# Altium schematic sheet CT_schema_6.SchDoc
size 251 x 159 mm
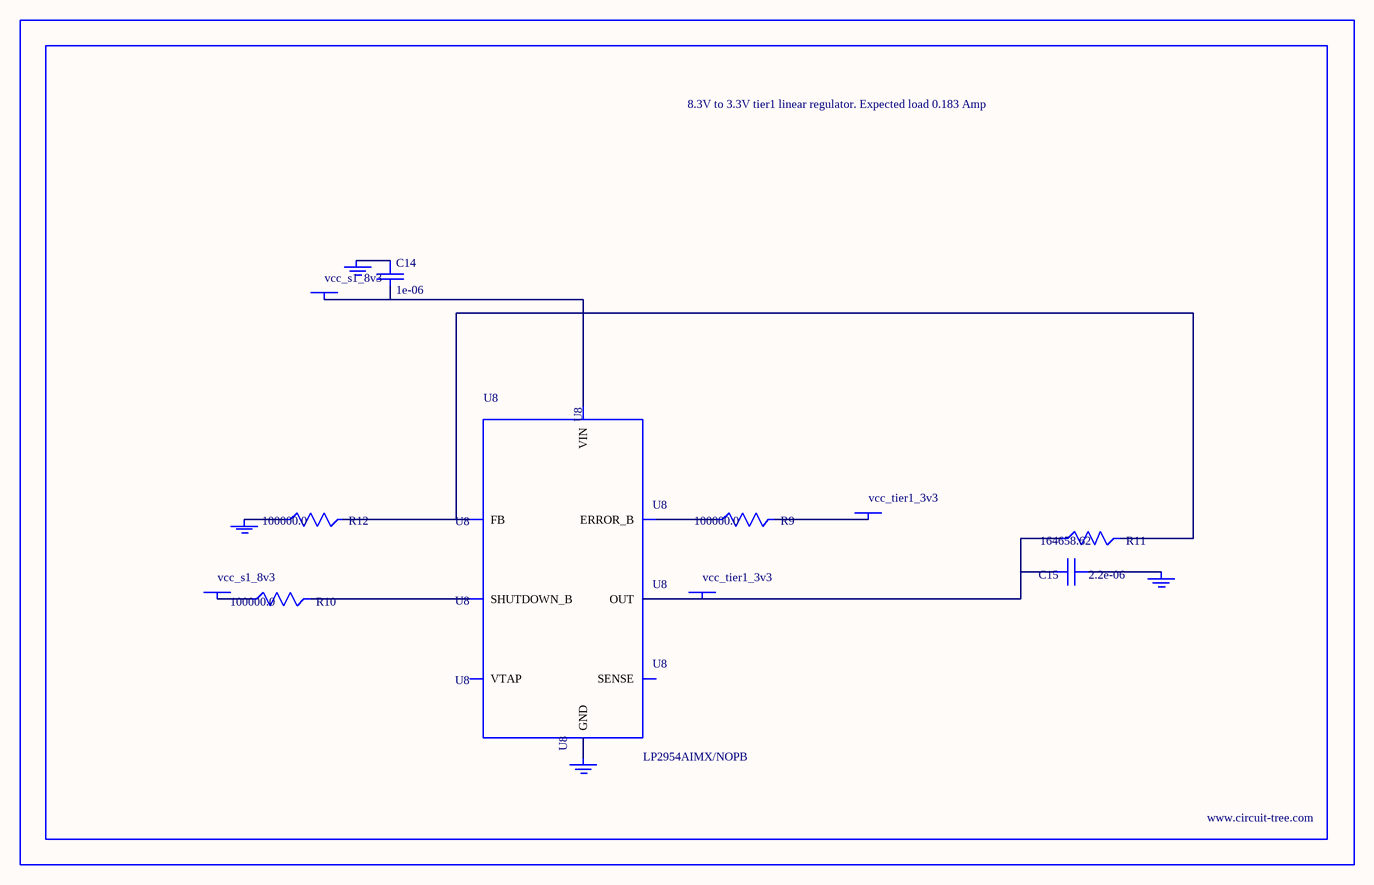
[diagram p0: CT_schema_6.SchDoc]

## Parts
BORDER5  (no value)
C14  1e-06  [EXV-9B]
C15  2.2e-06  [EXV-9B]
GND_INSTANCE_5_0  (no value)
GND_INSTANCE_5_1  (no value)
GND_INSTANCE_5_2  (no value)
GND_INSTANCE_5_3  (no value)
POWER_INSTANCE_5_0  vcc_s1_8v3
POWER_INSTANCE_5_1  vcc_tier1_3v3
POWER_INSTANCE_5_2  vcc_s1_8v3
POWER_INSTANCE_5_3  vcc_tier1_3v3
R9  100000.0  [R0603]
R10  100000.0  [R0603]
R11  164658.62  [R0603]
R12  100000.0  [R0603]
U8  LP2954AIMX/NOPB  [LP2954]

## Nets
NetC14_1: C14.1 GND_INSTANCE_5_2.0(GND)
NetC14_2: C14.2 POWER_INSTANCE_5_2.0(PWR) U8.8(VIN)
NetC15_1: C15.1 GND_INSTANCE_5_0.0(GND)
NetC15_2: C15.2 POWER_INSTANCE_5_3.0(PWR) R11.1 U8.1(OUT)
NetGND_INSTANCE_5_1_0: GND_INSTANCE_5_1.0(GND) R12.1
NetGND_INSTANCE_5_3_0: GND_INSTANCE_5_3.0(GND) U8.4(GND)
NetPOWER_INSTANCE_5_0_0: POWER_INSTANCE_5_0.0(PWR) R10.1
NetPOWER_INSTANCE_5_1_0: POWER_INSTANCE_5_1.0(PWR) R9.2
NetR9_1: R9.1 U8.5(ERROR_B)
NetR10_2: R10.2 U8.3(SHUTDOWN_B)
NetR11_2: R11.2 R12.2 U8.7(FB)

Not connected (* = marked no-connect by the designer): U8 2(SENSE) 6(VTAP)

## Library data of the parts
BORDER5 = BORDER_PAGE5
C14 = EDK105M050A9BAA
C15 = EDK225M050A9BAA
GND_INSTANCE_5_0-GND_INSTANCE_5_3 = GND
POWER_INSTANCE_5_0-POWER_INSTANCE_5_3 = PWR
R9 R10 R12 = RC0603JR-07100KL
R11 = R11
